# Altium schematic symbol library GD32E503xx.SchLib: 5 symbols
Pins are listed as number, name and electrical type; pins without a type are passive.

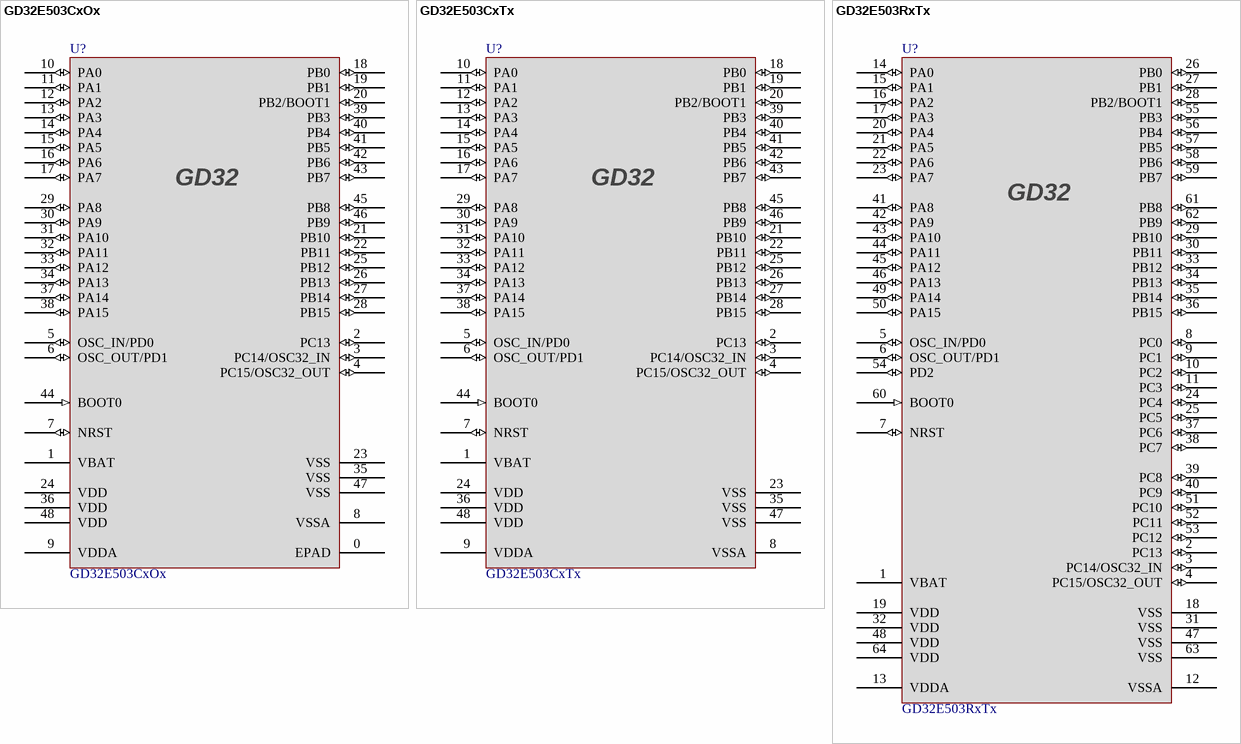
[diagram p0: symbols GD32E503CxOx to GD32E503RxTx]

## GD32E503CxOx
designator U?
footprint QFN48_5X5X0.6
pins: 0 EPAD (power), 1 VBAT (power), 2 PC13 (io), 3 PC14/OSC32_IN (io), 4 PC15/OSC32_OUT (io), 5 OSC_IN/PD0 (io), 6 OSC_OUT/PD1 (io), 7 NRST (io), 8 VSSA (power), 9 VDDA (power), 10 PA0 (io), 11 PA1 (io), 12 PA2 (io), 13 PA3 (io), 14 PA4 (io), 15 PA5 (io), 16 PA6 (io), 17 PA7 (io), 18 PB0 (io), 19 PB1 (io), 20 PB2/BOOT1 (io), 21 PB10 (io), 22 PB11 (io), 23 VSS (power), 24 VDD (power), 25 PB12 (io), 26 PB13 (io), 27 PB14 (io), 28 PB15 (io), 29 PA8 (io), 30 PA9 (io), 31 PA10 (io), 32 PA11 (io), 33 PA12 (io), 34 PA13 (io), 35 VSS (power), 36 VDD (power), 37 PA14 (io), 38 PA15 (io), 39 PB3 (io), 40 PB4 (io), 41 PB5 (io), 42 PB6 (io), 43 PB7 (io), 44 BOOT0 (in), 45 PB8 (io), 46 PB9 (io), 47 VSS (power), 48 VDD (power)
2 alternate drawings of the same symbol

## GD32E503CxTx
designator U?
footprint LQFP48_7x7x1.6
pins: 1 VBAT (power), 2 PC13 (io), 3 PC14/OSC32_IN (io), 4 PC15/OSC32_OUT (io), 5 OSC_IN/PD0 (io), 6 OSC_OUT/PD1 (io), 7 NRST (io), 8 VSSA (power), 9 VDDA (power), 10 PA0 (io), 11 PA1 (io), 12 PA2 (io), 13 PA3 (io), 14 PA4 (io), 15 PA5 (io), 16 PA6 (io), 17 PA7 (io), 18 PB0 (io), 19 PB1 (io), 20 PB2/BOOT1 (io), 21 PB10 (io), 22 PB11 (io), 23 VSS (power), 24 VDD (power), 25 PB12 (io), 26 PB13 (io), 27 PB14 (io), 28 PB15 (io), 29 PA8 (io), 30 PA9 (io), 31 PA10 (io), 32 PA11 (io), 33 PA12 (io), 34 PA13 (io), 35 VSS (power), 36 VDD (power), 37 PA14 (io), 38 PA15 (io), 39 PB3 (io), 40 PB4 (io), 41 PB5 (io), 42 PB6 (io), 43 PB7 (io), 44 BOOT0 (in), 45 PB8 (io), 46 PB9 (io), 47 VSS (power), 48 VDD (power)
2 alternate drawings of the same symbol

## GD32E503RxTx
designator U?
footprint LQPF64_10x10x1.6
pins: 1 VBAT (power), 2 PC13 (io), 3 PC14/OSC32_IN (io), 4 PC15/OSC32_OUT (io), 5 OSC_IN/PD0 (io), 6 OSC_OUT/PD1 (io), 7 NRST (io), 8 PC0 (io), 9 PC1 (io), 10 PC2 (io), 11 PC3 (io), 12 VSSA (power), 13 VDDA (power), 14 PA0 (io), 15 PA1 (io), 16 PA2 (io), 17 PA3 (io), 18 VSS (power), 19 VDD (power), 20 PA4 (io), 21 PA5 (io), 22 PA6 (io), 23 PA7 (io), 24 PC4 (io), 25 PC5 (io), 26 PB0 (io), 27 PB1 (io), 28 PB2/BOOT1 (io), 29 PB10 (io), 30 PB11 (io), 31 VSS (power), 32 VDD (power), 33 PB12 (io), 34 PB13 (io), 35 PB14 (io), 36 PB15 (io), 37 PC6 (io), 38 PC7 (io), 39 PC8 (io), 40 PC9 (io), 41 PA8 (io), 42 PA9 (io), 43 PA10 (io), 44 PA11 (io), 45 PA12 (io), 46 PA13 (io), 47 VSS (power), 48 VDD (power), 49 PA14 (io), 50 PA15 (io), 51 PC10 (io), 52 PC11 (io), 53 PC12 (io), 54 PD2 (io), 55 PB3 (io), 56 PB4 (io), 57 PB5 (io), 58 PB6 (io), 59 PB7 (io), 60 BOOT0 (in), 61 PB8 (io), 62 PB9 (io), 63 VSS (power), 64 VDD (power)
2 alternate drawings of the same symbol

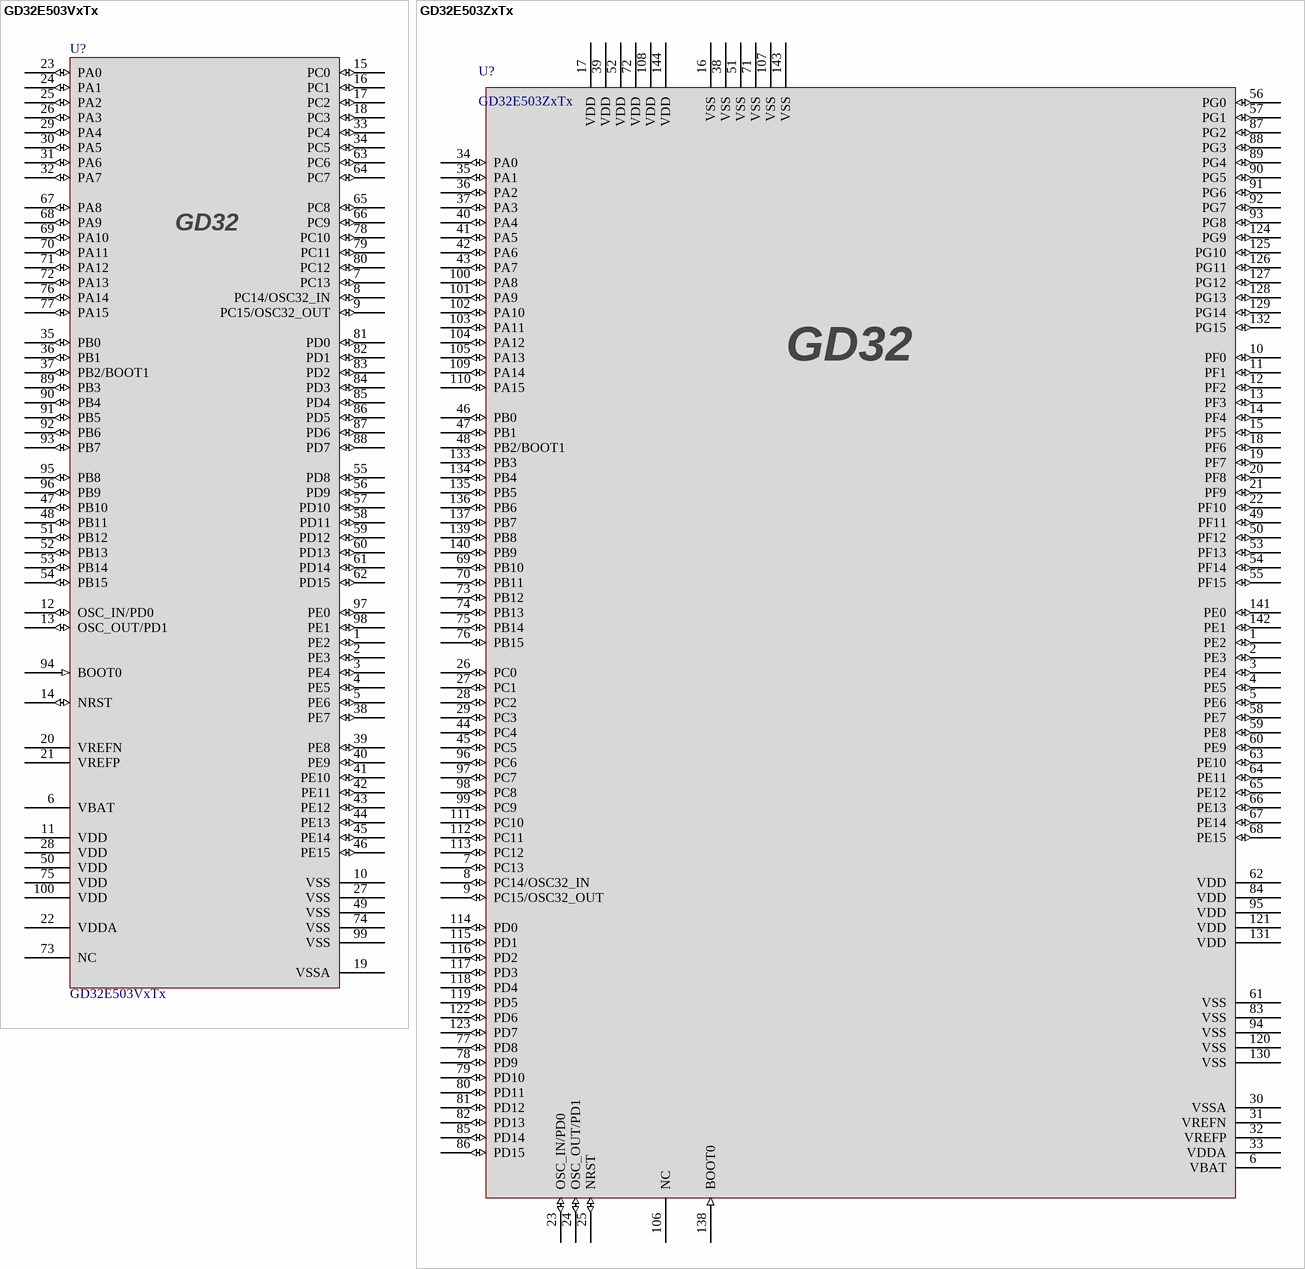
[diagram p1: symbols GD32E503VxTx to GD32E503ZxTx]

## GD32E503VxTx
designator U?
footprint LQFP100_14x14x1.6
pins: 1 PE2 (io), 2 PE3 (io), 3 PE4 (io), 4 PE5 (io), 5 PE6 (io), 6 VBAT (power), 7 PC13 (io), 8 PC14/OSC32_IN (io), 9 PC15/OSC32_OUT (io), 10 VSS (power), 11 VDD (power), 12 OSC_IN/PD0 (io), 13 OSC_OUT/PD1 (io), 14 NRST (io), 15 PC0 (io), 16 PC1 (io), 17 PC2 (io), 18 PC3 (io), 19 VSSA (power), 20 VREFN (power), 21 VREFP (power), 22 VDDA (power), 23 PA0 (io), 24 PA1 (io), 25 PA2 (io), 26 PA3 (io), 27 VSS (power), 28 VDD (power), 29 PA4 (io), 30 PA5 (io), 31 PA6 (io), 32 PA7 (io), 33 PC4 (io), 34 PC5 (io), 35 PB0 (io), 36 PB1 (io), 37 PB2/BOOT1 (io), 38 PE7 (io), 39 PE8 (io), 40 PE9 (io), 41 PE10 (io), 42 PE11 (io), 43 PE12 (io), 44 PE13 (io), 45 PE14 (io), 46 PE15 (io), 47 PB10 (io), 48 PB11 (io), 49 VSS (power), 50 VDD (power), 51 PB12 (io), 52 PB13 (io), 53 PB14 (io), 54 PB15 (io), 55 PD8 (io), 56 PD9 (io), 57 PD10 (io), 58 PD11 (io), 59 PD12 (io), 60 PD13 (io), 61 PD14 (io), 62 PD15 (io), 63 PC6 (io), 64 PC7 (io), 65 PC8 (io), 66 PC9 (io), 67 PA8 (io), 68 PA9 (io), 69 PA10 (io), 70 PA11 (io), 71 PA12 (io), 72 PA13 (io), 73 NC, 74 VSS (power), 75 VDD (power), 76 PA14 (io), 77 PA15 (io), 78 PC10 (io), 79 PC11 (io), 80 PC12 (io), 81 PD0 (io), 82 PD1 (io), 83 PD2 (io), 84 PD3 (io), 85 PD4 (io), 86 PD5 (io), 87 PD6 (io), 88 PD7 (io), 89 PB3 (io), 90 PB4 (io), 91 PB5 (io), 92 PB6 (io), 93 PB7 (io), 94 BOOT0 (in), 95 PB8 (io), 96 PB9 (io), 97 PE0 (io), 98 PE1 (io), 99 VSS (power), 100 VDD (power)
2 alternate drawings of the same symbol

## GD32E503ZxTx
designator U?
footprint LQFP144_20x20X1.6
pins: 1 PE2 (io), 2 PE3 (io), 3 PE4 (io), 4 PE5 (io), 5 PE6 (io), 6 VBAT (power), 7 PC13 (io), 8 PC14/OSC32_IN (io), 9 PC15/OSC32_OUT (io), 10 PF0 (io), 11 PF1 (io), 12 PF2 (io), 13 PF3 (io), 14 PF4 (io), 15 PF5 (io), 16 VSS (power), 17 VDD (power), 18 PF6 (io), 19 PF7 (io), 20 PF8 (io), 21 PF9 (io), 22 PF10 (io), 23 OSC_IN/PD0 (io), 24 OSC_OUT/PD1 (io), 25 NRST (io), 26 PC0 (io), 27 PC1 (io), 28 PC2 (io), 29 PC3 (io), 30 VSSA (power), 31 VREFN (power), 32 VREFP (power), 33 VDDA (power), 34 PA0 (io), 35 PA1 (io), 36 PA2 (io), 37 PA3  (io), 38 VSS (power), 39 VDD (power), 40 PA4 (io), 41 PA5 (io), 42 PA6 (io), 43 PA7 (io), 44 PC4 (io), 45 PC5 (io), 46 PB0 (io), 47 PB1 (io), 48 PB2/BOOT1 (io), 49 PF11 (io), 50 PF12 (io), 51 VSS (power), 52 VDD (power), 53 PF13 (io), 54 PF14 (io), 55 PF15 (io), 56 PG0 (io), 57 PG1 (io), 58 PE7 (io), 59 PE8 (io), 60 PE9 (io), 61 VSS (power), 62 VDD (power), 63 PE10 (io), 64 PE11 (io), 65 PE12 (io), 66 PE13 (io), 67 PE14 (io), 68 PE15 (io), 69 PB10 (io), 70 PB11 (io), 71 VSS (power), 72 VDD (power), 73 PB12 (io), 74 PB13 (io), 75 PB14 (io), 76 PB15 (io), 77 PD8 (io), 78 PD9 (io), 79 PD10 (io), 80 PD11 (io), 81 PD12 (io), 82 PD13 (io), 83 VSS (power), 84 VDD (power), 85 PD14 (io), 86 PD15 (io), 87 PG2 (io), 88 PG3 (io), 89 PG4 (io), 90 PG5 (io), 91 PG6 (io), 92 PG7 (io), 93 PG8 (io), 94 VSS (power), 95 VDD (power), 96 PC6 (io), 97 PC7 (io), 98 PC8 (io), 99 PC9 (io), 100 PA8 (io), 101 PA9 (io), 102 PA10 (io), 103 PA11 (io), 104 PA12 (io), 105 PA13 (io), 106 NC, 107 VSS (power), 108 VDD (power), 109 PA14 (io), 110 PA15 (io), 111 PC10 (io), 112 PC11 (io), 113 PC12 (io), 114 PD0 (io), 115 PD1 (io), 116 PD2 (io), 117 PD3 (io), 118 PD4 (io), 119 PD5 (io), 120 VSS (power), 121 VDD (power), 122 PD6 (io), 123 PD7 (io), 124 PG9 (io), 125 PG10 (io), 126 PG11 (io), 127 PG12 (io), 128 PG13 (io), 129 PG14 (io), 130 VSS (power), 131 VDD (power), 132 PG15 (io), 133 PB3 (io), 134 PB4 (io), 135 PB5 (io), 136 PB6 (io), 137 PB7 (io), 138 BOOT0 (in), 139 PB8 (io), 140 PB9 (io), 141 PE0 (io), 142 PE1 (io), 143 VSS (power), 144 VDD (power)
